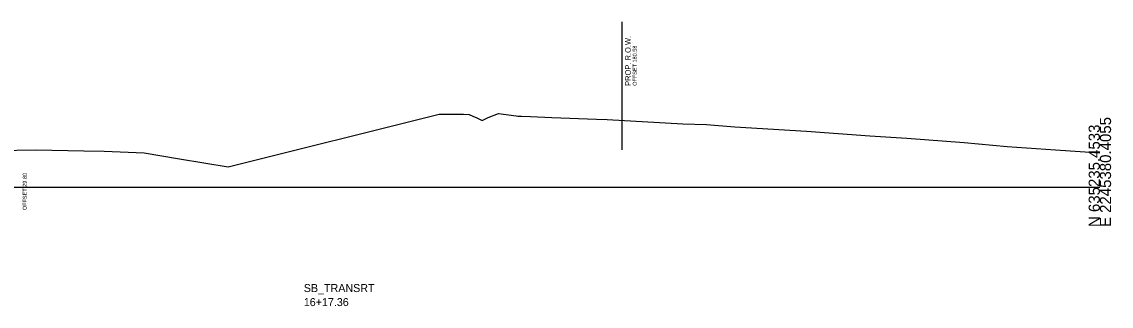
# Model space of a CAD drawing. Extents: x -26 to 669, y -22 to 6560.
# Drawn here: x 330.5 to 602.8, y 6470.2 to 6541.3 of the extents above; entities that cross this region are included whole.
import ezdxf

# ---------------------------------------------------------------- set-up
doc = ezdxf.new("R2010")
doc.units = 0
for name, color, linetype in [('DESIGN - ROW - Right-of-Way and Easement Labels', 7, 'Continuous'), ('DESIGN - ROW - Right-of-Way Linework', 7, 'Continuous'), ('DESIGN - SHEET - Light Grid', 7, 'Continuous'), ('DESIGN - TYPICAL - Subgrade Tie Text', 7, 'Continuous'), ('DESIGN - TYPICAL - Warning Text', 7, 'Continuous'), ('SURVEY - GROUND - Top of Ground', 7, 'Continuous')]:
    doc.layers.add(name, color=color, linetype=linetype)

msp = doc.modelspace()

# ---------------------------------------------------------------- linework, layer by layer
at = {"layer": 'DESIGN - ROW - Right-of-Way Linework'}
msp.add_line((480.58, 6509.28), (480.58, 6541.28), dxfattribs=at)
at = {"layer": 'DESIGN - SHEET - Light Grid'}
msp.add_line((300, 6500), (600, 6500), dxfattribs=at)
at = {"layer": 'SURVEY - GROUND - Top of Ground'}
for p, q in [((382.08, 6505.03), (434.82, 6518.22)), ((322, 6509.04), (334, 6509.28)), ((334, 6509.28), (346, 6509.04)), ((346, 6509.04), (351.08, 6508.93)), ((351.08, 6508.93), (361.08, 6508.53)), ((361.08, 6508.53), (369.95, 6507.06)), ((369.95, 6507.06), (382.08, 6505.03))]:
    msp.add_line(p, q, dxfattribs=at)
msp.add_lwpolyline([(434.82, 6518.22), (440.01, 6518.18), (440.94, 6518.17), (442.36, 6518.15), (443.25, 6517.74), (444.22, 6517.29), (445.59, 6516.63), (447.12, 6517.4), (449.63, 6518.37), (454.1, 6517.79), (454.46, 6517.73), (455.44, 6517.73), (457.63, 6517.6), (463, 6517.34), (474.13, 6516.98), (476.85, 6516.89), (495.71, 6515.82), (501.68, 6515.58), (508.77, 6515.06), (526.68, 6513.94), (542.53, 6512.8), (551.74, 6512.18), (566.11, 6511.11), (576.79, 6510.16), (588.94, 6509.28), (600, 6508.56)], dxfattribs=at)

# ---------------------------------------------------------------- texts
at = {"layer": 'DESIGN - ROW - Right-of-Way and Easement Labels'}
for s, height, p in [('PROP. R.O.W.', 1.4, (482.73, 6525.28)), ('OFFSET 180.58', 1, (484.23, 6525.28))]:
    msp.add_text(s, height=height, rotation=90, dxfattribs=at).set_placement(p)
at = {"layer": 'DESIGN - SHEET - Light Grid'}
for s, p in [('E 2245380.4055', (602.8, 6490)), ('N 635235.4533', (600, 6490))]:
    msp.add_text(s, height=2.8, rotation=90, dxfattribs=at).set_placement(p)
at = {"layer": 'DESIGN - TYPICAL - Subgrade Tie Text'}
msp.add_text('OFFSET 29.80', height=1, rotation=90, dxfattribs=at).set_placement((331.75, 6494.22))
at = {"layer": 'DESIGN - TYPICAL - Warning Text'}
for s, p in [('SB_TRANSRT', (401, 6473.75)), ('16+17.36', (401, 6470.25))]:
    msp.add_text(s, height=2, dxfattribs=at).set_placement(p)

doc.saveas('drawing.dxf')
